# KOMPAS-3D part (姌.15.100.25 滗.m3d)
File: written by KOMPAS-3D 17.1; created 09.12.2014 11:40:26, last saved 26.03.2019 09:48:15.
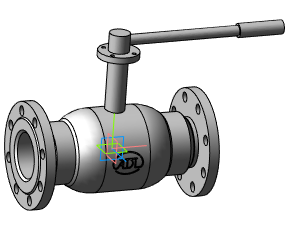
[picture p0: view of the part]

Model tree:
1. Операция без истории:5  (labels: Сталь 20  ГОСТ 1050-88)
